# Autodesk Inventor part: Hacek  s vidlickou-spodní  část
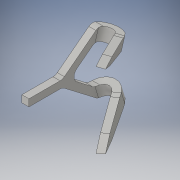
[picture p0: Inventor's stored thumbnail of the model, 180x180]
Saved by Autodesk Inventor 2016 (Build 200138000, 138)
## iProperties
Created: 2015-07
Part Number: Hacek  s vidlickou-spodní  část
Material: Generic
Document SubType Name: Modeling
Designer: brecka
Density: 1 g/cm^3
Appearance: Default
Author: brecka
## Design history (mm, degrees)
derived "Hacek  s vidlickou.ipt"
sketch "Náčrt1"
  geometry: L1 (186.029, 3.62)-(199.435, 13.907) reference; L2 (140.971, 3)-(184.202, 3) reference; L3 (123.869, 20.602)-(137.14, 4.786) reference; L4 (118.221, 25)-(123.869, 20.602) reference; L5 (121.571, 18.674)-(118.221, 25) reference; L6 (130.587, 7.928)-(121.571, 18.674) reference; L7 (4.502, 3)-(128.289, 3) reference; L8 (-10.734, -7.851)-(-10.204, -10.804) reference; L9 (184.202, 0)-(0, 0) reference; L10 (199.435, -10.907)-(186.029, -0.62) reference; L11 (199.08, -6.543)-(200.529, -11.436) reference; L12 (191.296, -0.88)-(197.986, -6.014) reference; L13 (197.986, 9.014)-(191.296, 3.88) reference; L14 (200.529, 14.436)-(199.08, 9.543) reference; L15 (-24.91, 38)-(150.971, 38); L16 (150.971, 38)-(150.971, -35); L17 (150.971, -35)-(-24.91, -35); L18 (-24.91, -35)-(-24.91, 38); L19 (150.971, -35)-(170.971, -35); L20 (170.971, -35)-(170.971, 38); L21 (170.971, 38)-(150.971, 38); L22 (150.971, 38)-(150.971, -35); L23 (170.971, 38)-(220.971, 38); L24 (220.971, 38)-(220.971, -35); L25 (220.971, -35)-(170.971, -35); L26 (170.971, -35)-(170.971, 38); A1 r 3 centre (201.262, 11.527) between (200.529, 14.436) and (199.435, 13.907) reference; A2 r 3 centre (184.202, 6) between (184.202, 3) and (186.029, 3.62) reference; A3 r 5 centre (140.971, 8) between (137.14, 4.786) and (140.971, 3) reference; A4 r 3 centre (128.289, 6) between (128.289, 3) and (130.587, 7.928) reference; A5 r 6 centre (4.502, 9) between (-0.983, 6.568) and (4.502, 3) reference; A6 r 12.5 centre (-12.41, 1.5) between (-0.983, 6.568) and (-10.204, -10.804) reference; A7 r 9.5 centre (-12.41, 1.5) between (-2.978, 2.64) and (-10.734, -7.851) reference; A8 r 3 centre (0, 3) between (-2.978, 2.64) and (0, 0) reference; A9 r 3 centre (184.202, -3) between (186.029, -0.62) and (184.202, 0) reference; A10 r 3 centre (201.262, -8.527) between (199.435, -10.907) and (200.529, -11.436) reference; A11 r 3 centre (199.812, -3.633) between (197.986, -6.014) and (199.08, -6.543) reference; A12 r 3 centre (193.122, 1.5) between (191.296, 3.88) and (191.296, -0.88) reference; A13 r 3 centre (199.812, 6.633) between (199.08, 9.543) and (197.986, 9.014) reference; A14 r 12.5 centre (-12.41, 1.5) between (-0.983, 6.568) and (-10.204, -10.804) reference; 1 further point
  constraints: 24 end point, 6 parallel, 3 horizontal, 3 perpendicular, 2 point on line, 1 tangent
  dimensions: "d1" = 20 distance of L20.end L21.end; "d2" = 10 distance from line of L2.start L16; "d3" = 35 distance between parallel lines of L9 L17; "d4" = 35 distance between parallel lines of L21 L2; "d6" = 50 distance of L20.end L23.end
extrude "Vysunutí1" cut sketch "Náčrt1" stored distance "d7" = 0; taper "d8" = 0 deg
feature "Těleso2::Hacek  s vidlickou.ipt" dims "d0" = 10
tag "Prvek štítků1"
node "Promítnutá smyčka1"
node "Těleso1"
